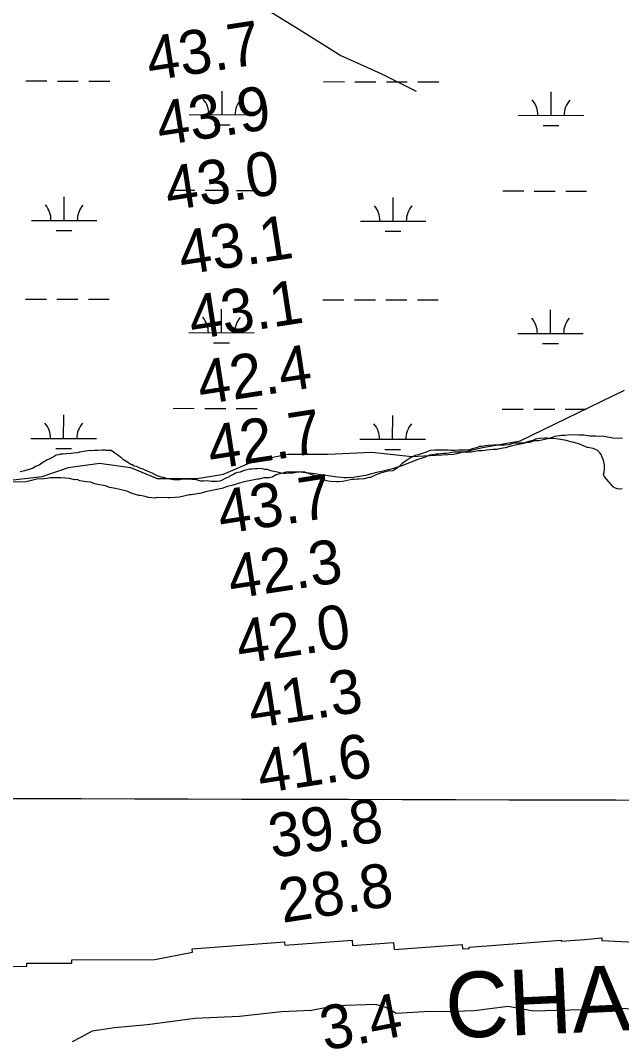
# Model space of a CAD drawing. Extents: x 3180038 to 3217926, y 922069 to 947485.
# Drawn here: x 3190059 to 3190976, y 933197 to 934753 of the extents above; entities that cross this region are included whole.
import ezdxf

# ---------------------------------------------------------------- set-up
doc = ezdxf.new("R2010")
doc.units = 0
for name, color, linetype in [('V-GRID-MAJR', 7, 'Continuous'), ('V-RIVR-EDGE', 7, 'Continuous'), ('V-RIVR-RANG', 7, 'Continuous'), ('V-RRAP-RVMT', 7, 'Continuous'), ('V-RRAP-RVMT-IDEN', 7, 'Continuous'), ('V-SITE-VEGE', 7, 'Continuous'), ('V-TOPO-SHOR', 7, 'Continuous'), ('V-WETL-SWMP', 7, 'Continuous')]:
    doc.layers.add(name, color=color, linetype=linetype)

msp = doc.modelspace()

# ---------------------------------------------------------------- linework, layer by layer
at = {"layer": 'V-GRID-MAJR'}
msp.add_spline([(3184280, 933581.8), (3186889.6, 933574.8), (3192108.7, 933561.5), (3197327.7, 933549), (3202546.8, 933537.2), (3207765.9, 933526.2), (3212985, 933516), (3215594.6, 933511.2)], degree=3, dxfattribs=at)
at = {"layer": 'V-RIVR-EDGE'}
msp.add_lwpolyline([(3191058.8, 933236.8), (3191046.9, 933236.8), (3191019.4, 933243.6), (3190974.3, 933246.3), (3190915.7, 933244.4), (3190841, 933242), (3190802.6, 933249.3), (3190750.8, 933242.7), (3190706.2, 933241.3), (3190682.8, 933241.9), (3190632, 933238.4), (3190615.9, 933247.7), (3190600.9, 933252.4), (3190539.2, 933250.5), (3190502.9, 933243.3), (3190457.2, 933240.9), (3190392.9, 933233.8), (3190324.9, 933230.8), (3190252.3, 933221.1), (3190202, 933216.6), (3190168.3, 933211.5), (3190150.1, 933202.2), (3190137.6, 933195.5)], dxfattribs=at)
at = {"layer": 'V-RRAP-RVMT'}
for points in [[(3189141.1, 933383.4), (3189258.8, 933373.1), (3189257.9, 933362), (3189391.9, 933350.2), (3189391.4, 933343.4), (3189522.8, 933332), (3189522.4, 933327.3), (3189607.3, 933319.8), (3189607.3, 933320.1), (3189728, 933309.5), (3189728, 933311.3), (3189795.8, 933309), (3189795.8, 933310.6), (3189864.6, 933308.3), (3189931.3, 933308.5), (3189931.3, 933310.4), (3190068.6, 933310.8), (3190068.6, 933315.2), (3190137.3, 933315.5)], [(3190137.3, 933315.5), (3190137.3, 933320.5), (3190263.7, 933320.9), (3190321.2, 933332.1), (3190320.7, 933337.4), (3190461.4, 933348.1), (3190461.8, 933342.9), (3190564.8, 933350.7), (3190565.5, 933342.2), (3190628, 933347), (3190628.9, 933336.2), (3190732.4, 933344.1), (3190733, 933337.1), (3190743.3, 933337.9), (3190743.2, 933339.9), (3190883.6, 933350.7), (3190883.7, 933349.1), (3190919.3, 933351.4), (3190945.7, 933353.8), (3190945.9, 933350.2), (3191025.3, 933345.9)]]:
    msp.add_lwpolyline(points, dxfattribs=at)
at = {"layer": 'V-SITE-VEGE'}
for points in [[(3190977.3, 934116.4), (3190970.6, 934115.5), (3190963, 934116.3), (3190948.6, 934118.6), (3190935.9, 934119.3), (3190927.4, 934119.2), (3190918.1, 934120.8), (3190910.5, 934120.7), (3190897.8, 934121.4), (3190889.4, 934120.4), (3190884.3, 934120.4), (3190874.2, 934118.5), (3190868.3, 934116.8), (3190863.2, 934115), (3190849.7, 934112.3), (3190843, 934112.2), (3190835.4, 934109.6), (3190831.2, 934109.5), (3190826.1, 934107.8), (3190816, 934106), (3190807.5, 934104.2), (3190798.3, 934101.5), (3190789, 934099.7), (3190785.6, 934098.8), (3190779.7, 934098.8), (3190770.4, 934097.8), (3190763.7, 934096.9), (3190756.9, 934096.8), (3190746.8, 934095), (3190719.7, 934094.6), (3190708.8, 934092.8), (3190704.5, 934092.8), (3190696.1, 934091.8), (3190693.5, 934091.8), (3190682.6, 934090), (3190675.9, 934087.3), (3190663.2, 934082.9), (3190654.8, 934079.5), (3190640.5, 934074.2), (3190627.9, 934069.8), (3190620.3, 934068), (3190610.2, 934065.4), (3190601.7, 934063.6), (3190594.1, 934061.8), (3190585.7, 934059.2), (3190566.3, 934056.4), (3190557, 934055.4), (3190552.8, 934055.4), (3190542.6, 934056.9), (3190513.8, 934060.8), (3190504.5, 934062.4), (3190493.5, 934063.1), (3190482.5, 934064.6), (3190463.9, 934064.4), (3190448.7, 934060), (3190442.9, 934056.5), (3190438.6, 934055.6), (3190430.2, 934055.5), (3190422.6, 934053.8), (3190420.1, 934053.7), (3190402.4, 934050.1), (3190392.2, 934047.5), (3190386.3, 934045.7), (3190381.3, 934043.9), (3190374.6, 934042.2), (3190366.1, 934039.5), (3190340.8, 934034.1), (3190334.9, 934032.4), (3190329, 934031.5), (3190318.9, 934029.6), (3190316.4, 934029.6), (3190301.2, 934026), (3190287.7, 934025), (3190284.3, 934025), (3190266.5, 934025.6), (3190264, 934024.7), (3190253.9, 934025.5), (3190248.8, 934027.1), (3190242, 934028.7), (3190239.4, 934028.7), (3190229.3, 934031.9), (3190220.8, 934035.2), (3190203.8, 934039.2), (3190194.5, 934040.8), (3190188.5, 934043.2), (3190179.2, 934044.8), (3190172.4, 934046.4), (3190165.6, 934048.9), (3190159.7, 934049.7), (3190149.5, 934051.2), (3190145.3, 934052.9), (3190141.1, 934052.8), (3190133.4, 934054.4)], [(3190133.4, 934054.4), (3190127.5, 934055.2), (3190119.9, 934055.9), (3190103.8, 934055.7), (3190098.8, 934054.8), (3190094.5, 934053.9), (3190083.6, 934053.8), (3190067.5, 934049.4), (3190044.7, 934049.1)]]:
    msp.add_lwpolyline(points, dxfattribs=at)
at = {"layer": 'V-TOPO-SHOR'}
for points in [[(3189730.2, 934743.5), (3189794.3, 934790.8), (3189875.4, 934804.3), (3189939.6, 934804.3), (3190003.8, 934804.3), (3190084.9, 934824.6), (3190162.5, 934834.7), (3190203.1, 934834.7), (3190263.9, 934834.7), (3190348.3, 934814.5), (3190402.4, 934794.2), (3190439.5, 934767.2), (3190483.5, 934740.2), (3190547.6, 934699.6), (3190608.4, 934672.6), (3190662.5, 934645.6)], [(3189879.6, 934065.4), (3189946.4, 934051.1), (3189983.5, 934040.9), (3190034.2, 934051.1), (3190091.6, 934057.8), (3190132.1, 934071.3), (3190179.4, 934078.1), (3190226.7, 934071.3), (3190267.3, 934054.4), (3190328.1, 934054.4), (3190368.6, 934061.2), (3190415.9, 934081.5), (3190466.6, 934091.6), (3190527.4, 934091.6), (3190594.9, 934095), (3190655.7, 934088.2), (3190719.9, 934091.6), (3190763.8, 934101.7), (3190821.2, 934111.9), (3190980, 934189.6)]]:
    msp.add_lwpolyline(points, dxfattribs=at)
at = {"layer": 'V-WETL-SWMP'}
for p, q in [((3190067, 934661), (3190099, 934661)), ((3190115, 934660.9), (3190147, 934660.9)), ((3190163, 934660.8), (3190195, 934660.7)), ((3190520.9, 934660), (3190552.9, 934659.9)), ((3190568.9, 934659.9), (3190600.9, 934659.8)), ((3190616.9, 934659.8), (3190648.9, 934659.7)), ((3190664.9, 934659.7), (3190696.9, 934659.6)), ((3190366.2, 934609.6), (3190366.3, 934645.6)), ((3190868.1, 934608.5), (3190868.2, 934644.5)), ((3190316.2, 934609.7), (3190416.2, 934609.5)), ((3190818.1, 934608.6), (3190918.1, 934608.4)), ((3190354.2, 934594.2), (3190378.2, 934594.2)), ((3190856.1, 934593.1), (3190880.1, 934593)), ((3190292.5, 934494.4), (3190324.5, 934494.3)), ((3190125.4, 934448.3), (3190125.5, 934484.3)), ((3190340.5, 934494.2), (3190372.5, 934494.2)), ((3190388.5, 934494.1), (3190420.5, 934494.1)), ((3190627.3, 934447.2), (3190627.4, 934483.2)), ((3190794.5, 934493.2), (3190826.5, 934493.2)), ((3190842.5, 934493.1), (3190874.5, 934493)), ((3190890.5, 934493), (3190922.5, 934492.9)), ((3190075.4, 934448.4), (3190175.4, 934448.2)), ((3190113.3, 934432.9), (3190137.3, 934432.8)), ((3190577.3, 934447.3), (3190677.3, 934447.1)), ((3190615.2, 934431.8), (3190639.2, 934431.7)), ((3190066.3, 934328.4), (3190098.3, 934328.3)), ((3190114.3, 934328.3), (3190146.3, 934328.2)), ((3190162.3, 934328.2), (3190194.3, 934328.1)), ((3190520.2, 934327.3), (3190552.2, 934327.3)), ((3190568.2, 934327.2), (3190600.2, 934327.2)), ((3190616.2, 934327.1), (3190648.2, 934327.1)), ((3190664.2, 934327), (3190696.2, 934327)), ((3190365.5, 934277), (3190365.5, 934313)), ((3190867.4, 934275.8), (3190867.4, 934311.8)), ((3190315.5, 934277.1), (3190415.5, 934276.8)), ((3190353.4, 934261.6), (3190377.4, 934261.5)), ((3190817.4, 934275.9), (3190917.4, 934275.7)), ((3190855.3, 934260.4), (3190879.3, 934260.4)), ((3190291.8, 934161.7), (3190323.8, 934161.6)), ((3190339.8, 934161.6), (3190371.8, 934161.5)), ((3190387.8, 934161.5), (3190419.8, 934161.4)), ((3190793.7, 934160.6), (3190825.7, 934160.5)), ((3190841.7, 934160.5), (3190873.7, 934160.4)), ((3190889.7, 934160.3), (3190921.7, 934160.3)), ((3190124.6, 934115.6), (3190124.7, 934151.6)), ((3190626.5, 934114.5), (3190626.6, 934150.5)), ((3190074.6, 934115.8), (3190174.6, 934115.5)), ((3190576.5, 934114.6), (3190676.5, 934114.4)), ((3190112.6, 934100.2), (3190136.6, 934100.2)), ((3190614.5, 934099.1), (3190638.5, 934099.1))]:
    msp.add_line(p, q, dxfattribs=at)
for points in [[(3190796.7, 934105.7), (3190793.5, 934105.7), (3190789.1, 934105.6), (3190784.6, 934105.6), (3190781, 934105.5), (3190772.1, 934105), (3190768.1, 934104.6), (3190762.5, 934103.7), (3190759.2, 934103.3), (3190754.4, 934101.6), (3190750, 934100.3), (3190744, 934098.6), (3190737.5, 934098.1), (3190733.1, 934098.1), (3190727.5, 934098), (3190721.4, 934097.1), (3190720.6, 934097.1), (3190718.2, 934097.1), (3190715, 934097.5), (3190711.3, 934097.8), (3190706.5, 934097.8), (3190699.6, 934098.1), (3190690.8, 934097.6), (3190683.9, 934097.1), (3190680.3, 934095.8), (3190677.5, 934094.6), (3190669.9, 934092.1), (3190665.5, 934090.8), (3190661, 934089.5), (3190653.8, 934086.2), (3190649.4, 934083.3), (3190646.2, 934080.9), (3190640.6, 934076.8), (3190635.5, 934071.9), (3190632.3, 934069.8), (3190629.1, 934067.8), (3190626.3, 934066.5), (3190619.8, 934065.6), (3190611.8, 934063.9), (3190607.8, 934062.7), (3190599.7, 934059.8), (3190595.7, 934057.7), (3190592.9, 934056.4), (3190591.3, 934056.4), (3190588.5, 934055.6), (3190583.3, 934054.3), (3190575.6, 934053.8), (3190572.4, 934053.4), (3190568.4, 934053.3), (3190563.9, 934053.3), (3190559.5, 934052), (3190550.7, 934050.3), (3190544.2, 934049.8), (3190541, 934049.8), (3190531.3, 934050), (3190525.7, 934051.2), (3190520.4, 934053.1), (3190513.5, 934056.3), (3190510.7, 934058.2), (3190507, 934059), (3190503.8, 934060.2), (3190496.9, 934062.9), (3190492.8, 934064.1), (3190488.8, 934064.8), (3190484, 934064.4), (3190479.5, 934063.9), (3190474.7, 934063), (3190471.1, 934062.6), (3190467.5, 934063), (3190463.8, 934062.5), (3190459.4, 934062.4), (3190456.2, 934062.8), (3190452.9, 934063.6), (3190448.1, 934064.7), (3190442.8, 934065.9), (3190439.2, 934067), (3190435.5, 934068.2), (3190431.5, 934068.6), (3190427.9, 934069.3), (3190424.6, 934069.7), (3190419.8, 934069.6), (3190416.6, 934069.6), (3190412.1, 934069.1), (3190408.9, 934068.7), (3190404.5, 934067.8), (3190400.5, 934067), (3190397.7, 934065.7), (3190393.7, 934064.5), (3190390.4, 934063.6), (3190386.8, 934062.8), (3190384, 934061.5), (3190380.4, 934059.1), (3190377.2, 934057.4), (3190372, 934055.3), (3190365.2, 934051.6), (3190362.8, 934050.8), (3190358, 934050.3), (3190354.3, 934050.3), (3190350.3, 934050.2), (3190343.8, 934050.9), (3190337.8, 934050.5)], [(3190976.9, 934039), (3190972.9, 934038.6), (3190969.7, 934038.9), (3190966.5, 934039.7), (3190962.8, 934041.7), (3190960.3, 934044.9), (3190953.4, 934053.2), (3190949.3, 934058), (3190948.4, 934061.3), (3190949.2, 934064.9), (3190949.6, 934068.1), (3190949.5, 934075.4), (3190948.2, 934082.2), (3190946.1, 934087), (3190944.4, 934091), (3190942.8, 934093.8), (3190938.7, 934097.8), (3190935.9, 934099), (3190932.6, 934100.2), (3190926.6, 934101.3), (3190924.6, 934102.1), (3190923.3, 934102.1), (3190920.1, 934103.6), (3190916.1, 934105.2), (3190910.8, 934107.6), (3190906.7, 934108.7), (3190901.5, 934109.9), (3190898.2, 934110.6), (3190891.8, 934112.6), (3190885.7, 934113.7), (3190882.5, 934114.1), (3190872, 934115.9), (3190870.4, 934115.9), (3190865.9, 934115.9), (3190862.3, 934116.2), (3190858.7, 934116.2), (3190851.8, 934115.7), (3190844.2, 934114.4), (3190840.2, 934112.7), (3190835.7, 934111.5), (3190826.1, 934108.5), (3190818.8, 934108.4), (3190813.2, 934108.4), (3190808, 934107.5), (3190804.4, 934106.2), (3190796.7, 934105.7)], [(3190337.8, 934050.5), (3190333.8, 934050.8), (3190327.3, 934052.7), (3190322, 934053.1), (3190320.4, 934053.1), (3190316, 934053.4), (3190303.5, 934052.9), (3190301.9, 934052.8), (3190298.3, 934052.8), (3190292.2, 934052.7), (3190284.1, 934054.2), (3190282.9, 934054.2), (3190277.2, 934056.2), (3190273.6, 934056.9), (3190270.8, 934057.7), (3190268.8, 934058.1), (3190265.5, 934059.6), (3190260.6, 934062.4), (3190256.2, 934064.4), (3190253.8, 934065.1), (3190246.1, 934068.7), (3190240.8, 934070.2), (3190235.9, 934073), (3190232.3, 934073.7), (3190229.8, 934075.3), (3190228.2, 934075.7), (3190218.5, 934081.6), (3190216, 934083.2), (3190212.8, 934086), (3190209.9, 934088.4), (3190207.1, 934090.4), (3190204.2, 934092.3), (3190200.6, 934094.7), (3190196.9, 934097.1), (3190193.3, 934097.5), (3190189.7, 934097.4), (3190188, 934097.8), (3190183.2, 934098.1), (3190176.8, 934097.2), (3190175.5, 934097.2), (3190171.5, 934097.2), (3190168.3, 934096.7), (3190165.1, 934097.1), (3190158.2, 934096.2), (3190157.8, 934096.2), (3190152.6, 934095.3), (3190148.6, 934094.9), (3190145.8, 934094), (3190139.7, 934093.2), (3190136.1, 934092.7), (3190129.2, 934092.2), (3190123.2, 934091.7), (3190120, 934091.7), (3190116.8, 934090.9), (3190113.1, 934090), (3190109.9, 934088), (3190105.5, 934085.9), (3190104.3, 934084.7), (3190099.5, 934083), (3190096.3, 934080.9), (3190091.5, 934078.1), (3190087.1, 934075.2), (3190085.5, 934074.3), (3190081.5, 934072.7), (3190077.9, 934070.6), (3190071.9, 934068.5), (3190069.9, 934067.7), (3190064.7, 934066.4), (3190059, 934064.7), (3190058.2, 934064.7)]]:
    msp.add_lwpolyline(points, dxfattribs=at)
for centre, start, end in [((3190311, 934610.2), 359.099, 40.6427), ((3190421.5, 934610), 139.099, 180.6426), ((3190812.9, 934609.1), 359.099, 40.6427), ((3190923.4, 934608.8), 139.099, 180.6426), ((3190070.1, 934448.9), 359.099, 40.6427), ((3190180.6, 934448.7), 139.099, 180.6426), ((3190572, 934447.8), 359.099, 40.6427), ((3190682.5, 934447.5), 139.099, 180.6426), ((3190310.2, 934277.6), 359.099, 40.6427), ((3190420.7, 934277.3), 139.099, 180.6426), ((3190812.1, 934276.4), 359.099, 40.6427), ((3190922.6, 934276.2), 139.099, 180.6426), ((3190069.4, 934116.2), 359.099, 40.6427), ((3190179.9, 934116), 139.099, 180.6426), ((3190571.3, 934115.1), 359.099, 40.6427), ((3190681.8, 934114.9), 139.099, 180.6426)]:
    msp.add_arc(centre, 35.2, start, end, dxfattribs=at)

# ---------------------------------------------------------------- texts
at = {"layer": 'V-RIVR-RANG'}
for s, rotation, p in [('43.7', 8.7983, (3190256.3, 934660.9)), ('43.9', 8.7983, (3190271.6, 934562)), ('43.0', 8.7983, (3190284.5, 934462.8)), ('43.1', 8.7983, (3190305.2, 934364.9)), ('43.1', 8.7983, (3190320.8, 934266.1)), ('42.4', 8.7983, (3190334, 934166.9)), ('42.7', 8.7983, (3190349.5, 934068.2)), ('43.7', 8.7983, (3190365, 933969.4)), ('42.3', 8.7983, (3190380.6, 933870.6)), ('42.0', 8.7983, (3190393.2, 933771.3)), ('41.3', 8.7983, (3190411.6, 933673)), ('41.6', 8.7983, (3190425.4, 933573.9)), ('39.8', 8.7983, (3190442.7, 933475.4)), ('28.8', 8.7983, (3190458.3, 933376.7)), ('3.4', 10.8806, (3190522.8, 933181.6))]:
    msp.add_text(s, height=67, rotation=rotation, dxfattribs=at).set_placement(p)
at = {"layer": 'V-RRAP-RVMT-IDEN'}
msp.add_text('CHANNEL', height=100, rotation=2.6277, dxfattribs=at).set_placement((3190709, 933200.3))

doc.saveas('drawing.dxf')
